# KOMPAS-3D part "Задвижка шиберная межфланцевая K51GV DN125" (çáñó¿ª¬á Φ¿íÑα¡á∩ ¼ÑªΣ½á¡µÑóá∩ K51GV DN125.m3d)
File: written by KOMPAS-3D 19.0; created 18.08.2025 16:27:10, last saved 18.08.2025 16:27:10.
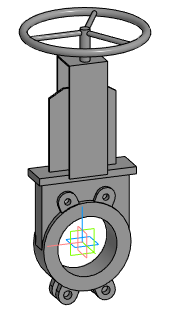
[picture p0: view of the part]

Document properties: Автор: Евгений; Полное имя файла: E:\Dendor Работа Сачек\3D для проектировщиков\2.4 Тип K51GV. Задвижка шиберная межфланцевая\stp_Задвижка шиберная K51GV DN50-400 с маховиком\Задвижка шиберная межфланцевая K51GV DN125.m3d

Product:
- Part/product: Задвижка шиберная межфланцевая K51GV DN125

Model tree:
1. Операция без истории:1  (labels: Задвижка шиберная межфланцевая K51GV DN125)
